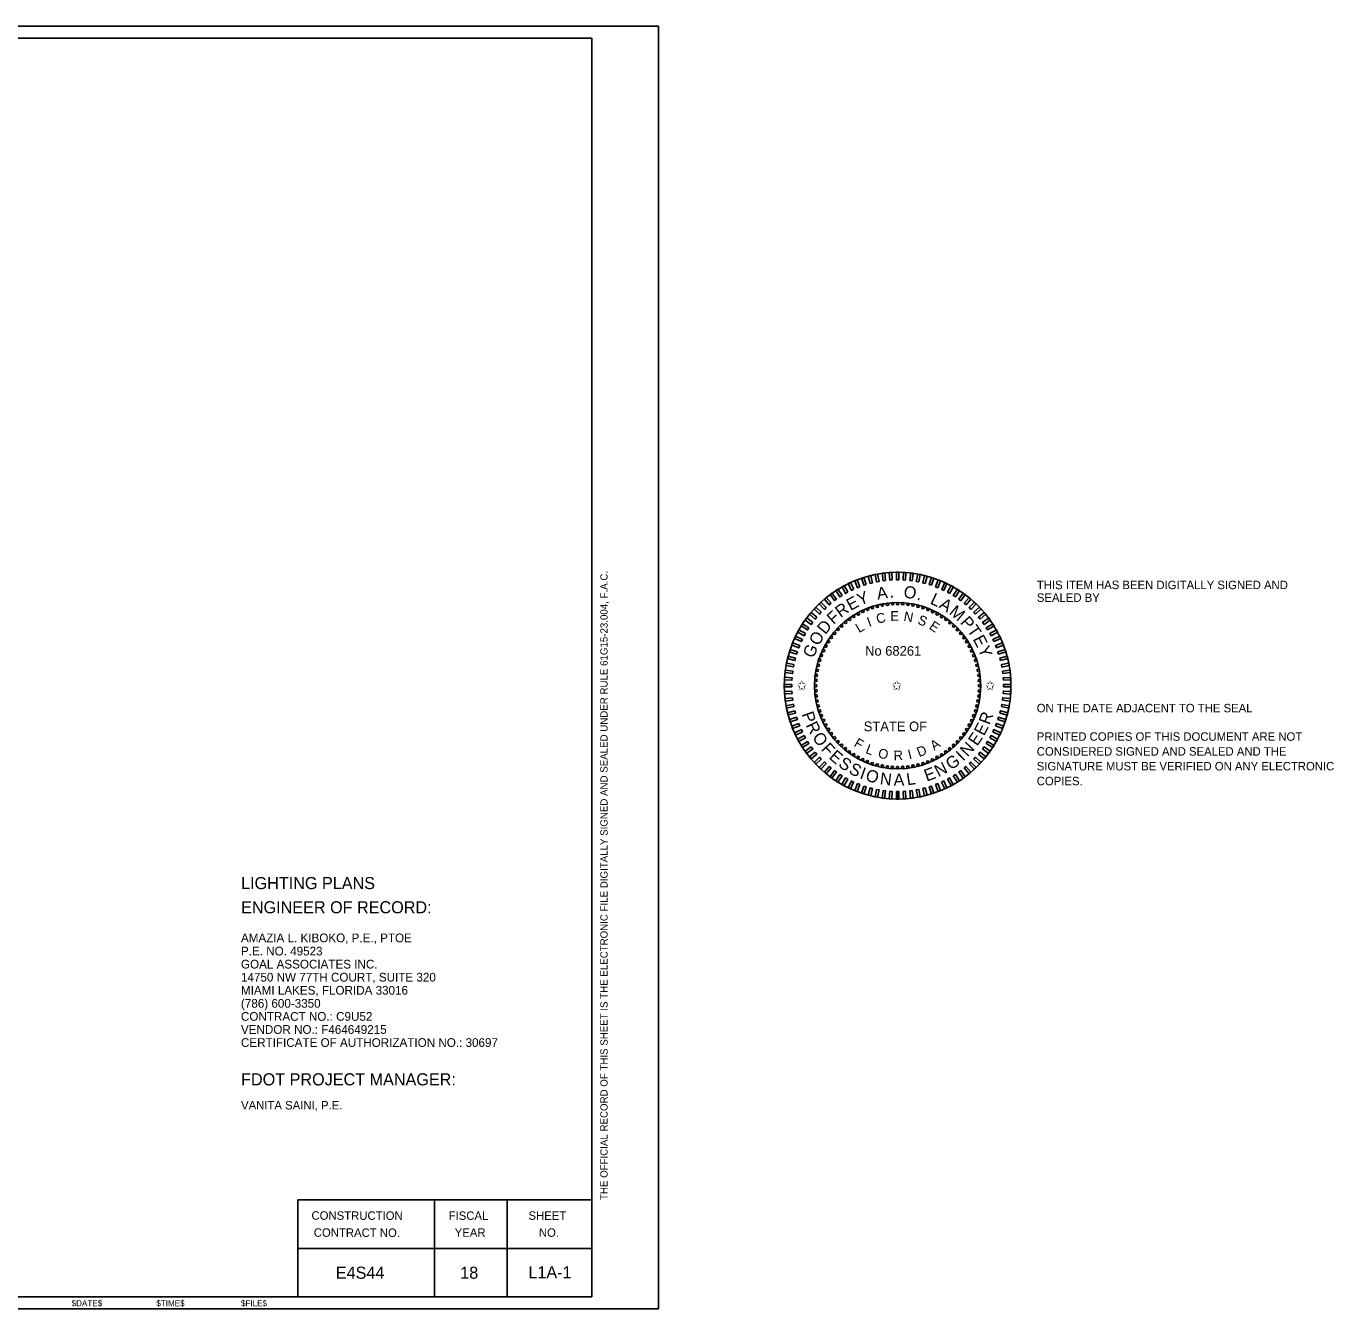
# Model space of a CAD drawing. Extents: x -820.2 to -798.1, y -2199.1 to -2182.2.
# Drawn here: x -808.95 to -798.14, y -2199.12 to -2188.52 of the extents above; entities that cross this region are included whole.
import ezdxf

# ---------------------------------------------------------------- set-up
doc = ezdxf.new("R2010")
doc.units = 0
for name, color, linetype in [('Logo_dp', 7, 'Continuous'), ('NonPlottingEle_dp', 7, 'Continuous'), ('PlotBorder_dp', 7, 'Continuous'), ('SheetBorder_dp', 7, 'Continuous'), ('SheetLines_dp', 7, 'Continuous'), ('TextLabel', 7, 'Continuous'), ('TextMinor', 7, 'Continuous'), ('TextMisc', 7, 'Continuous'), ('TextNotes', 7, 'Continuous')]:
    doc.layers.add(name, color=color, linetype=linetype)

msp = doc.modelspace()

# ---------------------------------------------------------------- linework, layer by layer
at = {"layer": 'Logo_dp'}
for p, q in [((-801.759, -2194.911), (-801.759, -2194.849)), ((-801.749, -2194.911), (-801.749, -2194.849)), ((-801.739, -2194.911), (-801.739, -2194.848))]:
    msp.add_line(p, q, dxfattribs=at)
for points in [[(-801.849, -2193.104), (-801.869, -2193.107), (-801.876, -2193.045), (-801.856, -2193.042)], [(-801.794, -2193.1), (-801.814, -2193.101), (-801.818, -2193.039), (-801.798, -2193.037)], [(-801.739, -2193.098), (-801.759, -2193.098), (-801.759, -2193.036), (-801.739, -2193.036)], [(-801.684, -2193.101), (-801.704, -2193.1), (-801.7, -2193.037), (-801.68, -2193.039)], [(-801.629, -2193.107), (-801.649, -2193.104), (-801.641, -2193.042), (-801.621, -2193.045)], [(-802.162, -2193.202), (-802.179, -2193.212), (-802.209, -2193.157), (-802.192, -2193.147)], [(-802.112, -2193.177), (-802.131, -2193.186), (-802.157, -2193.13), (-802.139, -2193.121)], [(-802.062, -2193.156), (-802.08, -2193.164), (-802.103, -2193.106), (-802.085, -2193.098)], [(-802.01, -2193.138), (-802.029, -2193.144), (-802.048, -2193.085), (-802.029, -2193.079)], [(-801.957, -2193.123), (-801.976, -2193.128), (-801.992, -2193.068), (-801.972, -2193.063)], [(-801.903, -2193.112), (-801.923, -2193.116), (-801.934, -2193.055), (-801.915, -2193.051)], [(-801.575, -2193.116), (-801.595, -2193.112), (-801.583, -2193.051), (-801.563, -2193.055)], [(-801.522, -2193.129), (-801.541, -2193.124), (-801.526, -2193.063), (-801.506, -2193.068)], [(-801.469, -2193.144), (-801.488, -2193.138), (-801.469, -2193.079), (-801.45, -2193.085)], [(-801.417, -2193.164), (-801.436, -2193.156), (-801.413, -2193.098), (-801.394, -2193.106)], [(-801.367, -2193.186), (-801.385, -2193.178), (-801.359, -2193.121), (-801.341, -2193.13)], [(-801.319, -2193.212), (-801.336, -2193.202), (-801.306, -2193.147), (-801.288, -2193.157)], [(-802.299, -2193.293), (-802.314, -2193.306), (-802.354, -2193.258), (-802.339, -2193.245)], [(-802.255, -2193.26), (-802.271, -2193.271), (-802.308, -2193.221), (-802.292, -2193.209)], [(-802.209, -2193.229), (-802.226, -2193.24), (-802.26, -2193.187), (-802.243, -2193.177)], [(-801.272, -2193.24), (-801.289, -2193.229), (-801.255, -2193.177), (-801.238, -2193.187)], [(-801.226, -2193.272), (-801.243, -2193.26), (-801.206, -2193.209), (-801.19, -2193.221)], [(-801.183, -2193.306), (-801.199, -2193.293), (-801.159, -2193.245), (-801.144, -2193.258)], [(-802.417, -2193.408), (-802.43, -2193.423), (-802.478, -2193.384), (-802.465, -2193.368)], [(-802.38, -2193.367), (-802.394, -2193.382), (-802.439, -2193.339), (-802.425, -2193.324)], [(-802.341, -2193.329), (-802.355, -2193.343), (-802.398, -2193.297), (-802.383, -2193.283)], [(-801.143, -2193.343), (-801.157, -2193.329), (-801.115, -2193.283), (-801.1, -2193.297)], [(-801.104, -2193.382), (-801.118, -2193.367), (-801.072, -2193.324), (-801.059, -2193.339)], [(-801.068, -2193.424), (-801.081, -2193.408), (-801.033, -2193.368), (-801.02, -2193.384)], [(-802.482, -2193.496), (-802.493, -2193.513), (-802.546, -2193.48), (-802.535, -2193.463)], [(-802.451, -2193.451), (-802.463, -2193.467), (-802.513, -2193.431), (-802.501, -2193.414)], [(-801.035, -2193.467), (-801.047, -2193.451), (-800.996, -2193.414), (-800.985, -2193.431)], [(-801.005, -2193.513), (-801.016, -2193.496), (-800.963, -2193.463), (-800.952, -2193.48)], [(-802.536, -2193.592), (-802.545, -2193.61), (-802.601, -2193.583), (-802.593, -2193.565)], [(-802.511, -2193.543), (-802.521, -2193.561), (-802.575, -2193.531), (-802.566, -2193.513)], [(-800.977, -2193.561), (-800.987, -2193.543), (-800.932, -2193.513), (-800.923, -2193.531)], [(-800.953, -2193.61), (-800.961, -2193.592), (-800.905, -2193.565), (-800.896, -2193.584)], [(-802.578, -2193.693), (-802.584, -2193.713), (-802.644, -2193.693), (-802.637, -2193.674)], [(-802.559, -2193.642), (-802.566, -2193.661), (-802.624, -2193.638), (-802.617, -2193.619)], [(-800.932, -2193.661), (-800.939, -2193.642), (-800.881, -2193.619), (-800.874, -2193.638)], [(-800.914, -2193.713), (-800.92, -2193.694), (-800.86, -2193.674), (-800.854, -2193.694)], [(-802.607, -2193.8), (-802.61, -2193.819), (-802.672, -2193.808), (-802.668, -2193.788)], [(-802.594, -2193.746), (-802.599, -2193.766), (-802.659, -2193.75), (-802.654, -2193.731)], [(-800.899, -2193.766), (-800.904, -2193.746), (-800.843, -2193.731), (-800.838, -2193.75)], [(-800.888, -2193.82), (-800.891, -2193.8), (-800.83, -2193.788), (-800.826, -2193.808)], [(-802.622, -2193.908), (-802.623, -2193.929), (-802.685, -2193.925), (-802.684, -2193.904)], [(-802.616, -2193.854), (-802.618, -2193.874), (-802.68, -2193.866), (-802.678, -2193.846)], [(-800.88, -2193.874), (-800.882, -2193.854), (-800.82, -2193.846), (-800.818, -2193.866)], [(-800.875, -2193.929), (-800.876, -2193.909), (-800.814, -2193.905), (-800.813, -2193.925)], [(-802.624, -2193.963), (-802.624, -2193.984), (-802.686, -2193.984), (-802.686, -2193.963)], [(-802.623, -2194.018), (-802.622, -2194.038), (-802.684, -2194.042), (-802.685, -2194.022)], [(-800.876, -2194.039), (-800.875, -2194.018), (-800.813, -2194.022), (-800.814, -2194.043)], [(-800.874, -2193.984), (-800.874, -2193.964), (-800.812, -2193.964), (-800.812, -2193.984)], [(-802.618, -2194.073), (-802.616, -2194.093), (-802.678, -2194.101), (-802.68, -2194.081)], [(-802.61, -2194.127), (-802.607, -2194.147), (-802.668, -2194.159), (-802.672, -2194.139)], [(-800.891, -2194.147), (-800.888, -2194.128), (-800.826, -2194.139), (-800.83, -2194.159)], [(-800.882, -2194.093), (-800.88, -2194.073), (-800.818, -2194.081), (-800.82, -2194.101)], [(-802.599, -2194.181), (-802.594, -2194.201), (-802.655, -2194.216), (-802.66, -2194.197)], [(-802.584, -2194.234), (-802.578, -2194.253), (-802.637, -2194.273), (-802.644, -2194.254)], [(-800.92, -2194.254), (-800.914, -2194.234), (-800.854, -2194.254), (-800.861, -2194.273)], [(-800.904, -2194.201), (-800.899, -2194.181), (-800.838, -2194.197), (-800.844, -2194.217)], [(-802.566, -2194.286), (-802.559, -2194.305), (-802.617, -2194.328), (-802.624, -2194.309)], [(-802.545, -2194.337), (-802.536, -2194.355), (-802.593, -2194.382), (-802.602, -2194.363)], [(-800.962, -2194.355), (-800.953, -2194.337), (-800.896, -2194.364), (-800.905, -2194.382)], [(-800.939, -2194.305), (-800.932, -2194.286), (-800.874, -2194.309), (-800.881, -2194.328)], [(-802.521, -2194.386), (-802.511, -2194.404), (-802.566, -2194.434), (-802.575, -2194.416)], [(-802.493, -2194.434), (-802.482, -2194.451), (-802.535, -2194.484), (-802.546, -2194.467)], [(-801.016, -2194.451), (-801.005, -2194.434), (-800.952, -2194.467), (-800.963, -2194.484)], [(-800.987, -2194.404), (-800.977, -2194.386), (-800.923, -2194.416), (-800.932, -2194.434)], [(-802.463, -2194.48), (-802.451, -2194.496), (-802.502, -2194.533), (-802.513, -2194.516)], [(-802.43, -2194.523), (-802.417, -2194.539), (-802.465, -2194.579), (-802.478, -2194.563)], [(-801.081, -2194.539), (-801.068, -2194.524), (-801.02, -2194.563), (-801.033, -2194.579)], [(-801.047, -2194.496), (-801.035, -2194.48), (-800.985, -2194.516), (-800.997, -2194.533)], [(-802.394, -2194.565), (-802.38, -2194.58), (-802.426, -2194.623), (-802.439, -2194.608)], [(-802.355, -2194.604), (-802.341, -2194.618), (-802.383, -2194.664), (-802.398, -2194.65)], [(-802.315, -2194.641), (-802.299, -2194.654), (-802.339, -2194.702), (-802.354, -2194.689)], [(-801.199, -2194.654), (-801.184, -2194.641), (-801.144, -2194.689), (-801.159, -2194.702)], [(-801.157, -2194.618), (-801.143, -2194.605), (-801.1, -2194.65), (-801.115, -2194.664)], [(-801.118, -2194.58), (-801.104, -2194.565), (-801.059, -2194.608), (-801.073, -2194.623)], [(-802.272, -2194.675), (-802.255, -2194.687), (-802.292, -2194.738), (-802.308, -2194.726)], [(-802.226, -2194.707), (-802.209, -2194.718), (-802.243, -2194.77), (-802.26, -2194.76)], [(-802.179, -2194.735), (-802.162, -2194.745), (-802.192, -2194.8), (-802.21, -2194.79)], [(-802.131, -2194.761), (-802.113, -2194.77), (-802.139, -2194.826), (-802.157, -2194.817)], [(-801.386, -2194.77), (-801.367, -2194.761), (-801.341, -2194.818), (-801.359, -2194.826)], [(-801.336, -2194.745), (-801.319, -2194.736), (-801.289, -2194.79), (-801.306, -2194.8)], [(-801.289, -2194.718), (-801.272, -2194.707), (-801.238, -2194.76), (-801.255, -2194.771)], [(-801.243, -2194.687), (-801.227, -2194.676), (-801.19, -2194.726), (-801.206, -2194.738)], [(-802.081, -2194.783), (-802.062, -2194.791), (-802.085, -2194.849), (-802.104, -2194.841)], [(-802.029, -2194.803), (-802.01, -2194.809), (-802.029, -2194.868), (-802.048, -2194.862)], [(-801.976, -2194.819), (-801.957, -2194.824), (-801.972, -2194.884), (-801.992, -2194.879)], [(-801.923, -2194.831), (-801.903, -2194.835), (-801.915, -2194.896), (-801.935, -2194.892)], [(-801.869, -2194.84), (-801.849, -2194.843), (-801.857, -2194.905), (-801.877, -2194.902)], [(-801.814, -2194.846), (-801.794, -2194.847), (-801.798, -2194.91), (-801.818, -2194.909)], [(-801.759, -2194.849), (-801.739, -2194.849), (-801.739, -2194.911), (-801.759, -2194.911)], [(-801.704, -2194.847), (-801.684, -2194.846), (-801.68, -2194.909), (-801.7, -2194.91)], [(-801.649, -2194.843), (-801.629, -2194.84), (-801.622, -2194.902), (-801.642, -2194.905)], [(-801.595, -2194.835), (-801.575, -2194.831), (-801.563, -2194.893), (-801.583, -2194.896)], [(-801.541, -2194.824), (-801.522, -2194.819), (-801.506, -2194.879), (-801.526, -2194.884)], [(-801.488, -2194.809), (-801.469, -2194.803), (-801.45, -2194.862), (-801.469, -2194.868)], [(-801.436, -2194.791), (-801.418, -2194.783), (-801.395, -2194.841), (-801.413, -2194.849)]]:
    msp.add_lwpolyline(points, close=True, dxfattribs=at)
for centre in [(-802.075, -2193.38), (-802.037, -2193.36), (-801.998, -2193.343), (-801.958, -2193.329), (-801.917, -2193.317), (-801.875, -2193.308), (-801.833, -2193.301), (-801.791, -2193.297), (-801.748, -2193.296), (-801.706, -2193.297), (-801.664, -2193.301), (-801.621, -2193.308), (-801.58, -2193.317), (-801.539, -2193.329), (-801.499, -2193.344), (-801.46, -2193.361), (-801.422, -2193.38), (-802.212, -2193.479), (-802.18, -2193.451), (-802.147, -2193.425), (-802.112, -2193.401), (-801.386, -2193.402), (-801.35, -2193.426), (-801.317, -2193.452), (-801.285, -2193.48), (-802.297, -2193.575), (-802.271, -2193.541), (-802.242, -2193.509), (-801.255, -2193.51), (-801.227, -2193.542), (-801.201, -2193.576), (-802.362, -2193.685), (-802.342, -2193.647), (-802.321, -2193.61), (-801.177, -2193.611), (-801.155, -2193.648), (-801.136, -2193.686), (-802.405, -2193.805), (-802.393, -2193.764), (-802.379, -2193.724), (-801.119, -2193.725), (-801.105, -2193.765), (-801.093, -2193.806), (-802.421, -2193.888), (-802.414, -2193.846), (-801.083, -2193.847), (-801.077, -2193.889), (-802.426, -2193.973), (-802.425, -2193.93), (-802.425, -2194.016), (-801.073, -2193.932), (-801.073, -2194.017), (-801.072, -2193.974), (-802.421, -2194.058), (-802.415, -2194.1), (-801.084, -2194.101), (-801.077, -2194.059), (-802.405, -2194.141), (-802.393, -2194.182), (-802.379, -2194.222), (-801.119, -2194.223), (-801.105, -2194.183), (-801.093, -2194.143), (-802.362, -2194.261), (-802.343, -2194.299), (-802.321, -2194.336), (-801.177, -2194.337), (-801.156, -2194.3), (-801.136, -2194.262), (-802.297, -2194.371), (-802.271, -2194.405), (-802.243, -2194.437), (-801.256, -2194.438), (-801.227, -2194.406), (-801.201, -2194.372), (-802.213, -2194.467), (-802.181, -2194.495), (-802.148, -2194.521), (-802.112, -2194.545), (-802.076, -2194.567), (-801.423, -2194.567), (-801.386, -2194.546), (-801.351, -2194.522), (-801.318, -2194.496), (-801.286, -2194.468), (-802.038, -2194.586), (-801.999, -2194.603), (-801.959, -2194.618), (-801.918, -2194.63), (-801.876, -2194.639), (-801.834, -2194.646), (-801.792, -2194.65), (-801.749, -2194.651), (-801.707, -2194.65), (-801.665, -2194.646), (-801.623, -2194.639), (-801.581, -2194.63), (-801.54, -2194.618), (-801.5, -2194.604), (-801.461, -2194.587)]:
    msp.add_circle(centre, 0.01, dxfattribs=at)
at = {"layer": 'NonPlottingEle_dp'}
for radius in [0.937, 0.687]:
    msp.add_circle((-801.749, -2193.974), radius, dxfattribs=at)
at = {"layer": 'PlotBorder_dp'}
msp.add_lwpolyline([(-820.227, -2199.124), (-803.727, -2199.124), (-803.727, -2188.524), (-820.227, -2188.524)], close=True, dxfattribs=at)
at = {"layer": 'SheetBorder_dp'}
for p, q in [((-819.677, -2188.624), (-804.277, -2188.624)), ((-804.277, -2188.624), (-804.277, -2199.024)), ((-819.677, -2199.024), (-804.277, -2199.024))]:
    msp.add_line(p, q, dxfattribs=at)
at = {"layer": 'SheetLines_dp'}
for p, q in [((-806.708, -2198.224), (-804.277, -2198.224)), ((-806.708, -2199.024), (-806.708, -2198.224)), ((-805.577, -2199.024), (-805.577, -2198.224)), ((-804.977, -2199.024), (-804.977, -2198.224)), ((-806.708, -2198.624), (-804.277, -2198.624))]:
    msp.add_line(p, q, dxfattribs=at)

# ---------------------------------------------------------------- texts
at = {"layer": 'Logo_dp'}
for s, height, rotation, p in [('A', 0.1, 8.8088, (-801.914, -2193.263)), ('O', 0.1, 352.1877, (-801.704, -2193.245)), ('E', 0.1, 28.1055, (-802.139, -2193.357)), ('Y', 0.1, 21.0633, (-802.061, -2193.314)), ('.', 0.1, 1.0418, (-801.816, -2193.247)), ('.', 0.1, 343.5268, (-801.595, -2193.261)), ('L', 0.1, 334.6727, (-801.487, -2193.293)), ('A', 0.1, 328.4096, (-801.414, -2193.325)), ('F', 0.1, 42.3772, (-802.279, -2193.473)), ('R', 0.1, 35.9269, (-802.22, -2193.416)), ('C', 0.08, 12.2025, (-801.917, -2193.462)), ('E', 0.08, 0.4186, (-801.809, -2193.438)), ('N', 0.08, 349.2914, (-801.704, -2193.437)), ('M', 0.1, 320.6426, (-801.33, -2193.377)), ('D', 0.1, 50.8569, (-802.347, -2193.556)), ('L', 0.08, 30.4021, (-802.068, -2193.54)), ('I', 0.08, 20.0117, (-801.985, -2193.489)), ('S', 0.08, 337.0221, (-801.591, -2193.459)), ('E', 0.08, 325.8663, (-801.495, -2193.499)), ('P', 0.1, 311.1966, (-801.237, -2193.454)), ('T', 0.1, 304.4563, (-801.18, -2193.517)), ('O', 0.1, 59.5178, (-802.403, -2193.651)), ('E', 0.1, 297.6315, (-801.13, -2193.588)), ('G', 0.1, 68.0518, (-802.444, -2193.752)), ('Y', 0.1, 290.5893, (-801.087, -2193.667)), ('P', 0.1, 289.4055, (-802.544, -2194.208)), ('R', 0.1, 69.5134, (-800.989, -2194.303)), ('R', 0.1, 296.1458, (-802.511, -2194.3)), ('E', 0.1, 62.4712, (-801.035, -2194.394)), ('O', 0.1, 303.9671, (-802.459, -2194.4)), ('F', 0.1, 312.628, (-802.387, -2194.502)), ('F', 0.08, 328.7241, (-802.117, -2194.47)), ('A', 0.08, 34.4992, (-801.447, -2194.513)), ('N', 0.1, 47.1788, (-801.171, -2194.567)), ('E', 0.1, 55.4289, (-801.092, -2194.478)), ('E', 0.1, 319.0783, (-802.323, -2194.571)), ('L', 0.08, 339.2916, (-802.02, -2194.529)), ('O', 0.08, 349.6821, (-801.915, -2194.569)), ('R', 0.08, 2.3398, (-801.781, -2194.591)), ('I', 0.08, 14.2037, (-801.653, -2194.584)), ('D', 0.08, 22.0128, (-801.571, -2194.565)), ('G', 0.1, 35.1115, (-801.308, -2194.675)), ('I', 0.1, 43.6456, (-801.209, -2194.602)), ('S', 0.1, 326.1206, (-802.246, -2194.637)), ('S', 0.1, 333.193, (-802.16, -2194.693)), ('I', 0.1, 340.2654, (-802.069, -2194.738)), ('O', 0.1, 343.7986, (-802.021, -2194.756)), ('E', 0.1, 19.8191, (-801.509, -2194.767)), ('N', 0.1, 26.8614, (-801.413, -2194.731)), ('N', 0.1, 352.4595, (-801.9, -2194.788)), ('A', 0.1, 0.7097, (-801.782, -2194.801)), ('L', 0.1, 8.4767, (-801.669, -2194.798))]:
    msp.add_text(s, height=height, rotation=rotation, dxfattribs=at).set_placement(p)
for s, p in [('No 68261', (-802.018, -2193.726)), ('✩', (-802.584, -2194.011)), ('✩', (-801.799, -2194.011)), ('✩', (-801.027, -2194.011)), ('STATE OF', (-802.029, -2194.35))]:
    msp.add_text(s, height=0.08, dxfattribs=at).set_placement(p)
at = {"layer": 'TextLabel'}
for s, height, p in [('LIGHTING PLANS', 0.1, (-807.177, -2195.655)), ('ENGINEER OF RECORD:', 0.1, (-807.177, -2195.855)), ('AMAZIA L. KIBOKO, P.E., PTOE', 0.07202, (-807.178, -2196.094)), ('P.E. NO. 49523', 0.07202, (-807.178, -2196.203)), ('GOAL ASSOCIATES INC. ', 0.07202, (-807.178, -2196.311)), ('14750 NW 77TH COURT, SUITE 320', 0.07202, (-807.178, -2196.419)), ('MIAMI LAKES, FLORIDA 33016', 0.07202, (-807.178, -2196.527)), ('(786) 600-3350', 0.07202, (-807.178, -2196.635)), ('CONTRACT NO.: C9U52', 0.07202, (-807.178, -2196.743)), ('VENDOR NO.: F464649215', 0.07202, (-807.178, -2196.851)), ('CERTIFICATE OF AUTHORIZATION NO.: 30697', 0.07202, (-807.178, -2196.959)), ('E4S44', 0.1, (-806.394, -2198.875)), ('18', 0.1, (-805.365, -2198.875)), ('L1A-1', 0.1, (-804.802, -2198.871))]:
    msp.add_text(s, height=height, dxfattribs=at).set_placement(p)
at = {"layer": 'TextMinor'}
for s, p in [('$DATE$', (-808.578, -2199.102)), ('$TIME$', (-807.878, -2199.102)), ('$FILE$', (-807.178, -2199.102))]:
    msp.add_text(s, height=0.05, rotation=360, dxfattribs=at).set_placement(p)
at = {"layer": 'TextMisc'}
msp.add_text('THE OFFICIAL RECORD OF THIS SHEET IS THE ELECTRONIC FILE DIGITALLY SIGNED AND SEALED UNDER RULE 61G15-23.004, F.A.C.', height=0.06, rotation=90, dxfattribs=at).set_placement((-804.147, -2198.224))
for s, p in [('THIS ITEM HAS BEEN DIGITALLY SIGNED AND ', (-800.598, -2193.176)), ('SEALED BY', (-800.598, -2193.281)), ('ON THE DATE ADJACENT TO THE SEAL', (-800.599, -2194.194)), ('PRINTED COPIES OF THIS DOCUMENT ARE NOT ', (-800.599, -2194.429)), ('CONSIDERED SIGNED AND SEALED AND THE ', (-800.599, -2194.552)), ('SIGNATURE MUST BE VERIFIED ON ANY ELECTRONIC ', (-800.599, -2194.674)), ('COPIES.', (-800.599, -2194.797))]:
    msp.add_text(s, height=0.07, dxfattribs=at).set_placement(p)
at = {"layer": 'TextNotes'}
for s, height, p in [('FDOT PROJECT MANAGER:', 0.1, (-807.177, -2197.277)), ('VANITA SAINI, P.E.', 0.07, (-807.177, -2197.476))]:
    msp.add_text(s, height=height, dxfattribs=at).set_placement(p)
for s, p in [('CONSTRUCTION', (-806.595, -2198.387)), ('FISCAL', (-805.461, -2198.388)), ('SHEET', (-804.801, -2198.388)), ('CONTRACT NO.', (-806.576, -2198.528)), ('YEAR', (-805.411, -2198.528)), ('NO.', (-804.715, -2198.528))]:
    msp.add_text(s, height=0.07, rotation=359.8607, dxfattribs=at).set_placement(p)

doc.saveas('drawing.dxf')
